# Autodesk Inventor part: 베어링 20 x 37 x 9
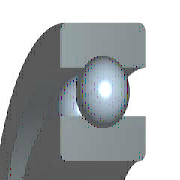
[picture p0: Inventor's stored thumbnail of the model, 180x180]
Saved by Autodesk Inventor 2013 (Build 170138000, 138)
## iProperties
IsCustomPart: 1
Created: 2012-02
Part Number: 베어링 20 x 37 x 9
Material: 강철, 연강
Description: 깊은 그루브 볼 베어링
Document SubType Name: Modeling
Standard: KS B 2023
Designer: mduedu
Standards Organization: KS
Language: ko-KR
Size Designation: 6904 - 20 x 37 x 9
Categories: <MemberInstance><Categories><Category DisplayName="샤프트 부품" InternalName="7f7aeb1f-a693-4053-b835-cee3144e0d98" Mnemonic="SHFT"><Category DisplayName="베어링" Inter
Density: 7.86 g/cm^3
Mass: 36.2614 g
Surface Area: 48.5817 cm^2
Volume: 4.61341 cm^3
Author: mduedu
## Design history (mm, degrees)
sketch "스케치" dims "d0" = 4.42 (= -0.26 x WD + 0.26 x BD)
  geometry: L1 (2.29, 14.25)-(6.71, 14.25); L2 (4.5, 14.25)-(4.5, 12.04); L3 (4.5, 14.25)-(4.5, 16.46); L4 (2.858, 12.771)-(0, 12.771); L5 (0, 10)-(9, 10); L6 (2.858, 15.729)-(0, 15.729); L7 (0, 18.5)-(9, 18.5); L8 (9, 10)-(9, 12.771); L9 (6.142, 12.771)-(9, 12.771); L10 (6.142, 15.729)-(9, 15.729); L11 (9, 18.5)-(9, 15.729); L12 (-1.4, 0)-(8.4, 0) reference; L13 (0, -0.3)-(0, 5.3) reference
  constraints: 22 end point, 4 point on line, 2 collinear, 2 perpendicular, 2 symmetric about line, 1 midpoint, 1 parallel, 14 other
  dimensions: "d9" = 20 diameter of L5 L12 (= WD); "d11" = 37 diameter of L7 L12 (= BD); "d12" = 9 distance between parallel lines of L8 L13 (= KB); "d13" = 25.542 diameter of L9 L12 (= 0.326 x BD + 0.674 x WD)
revolve "본체" stored, may be unused: angle "d6" = 90 deg
revolve "볼" stored, may be unused: angle "d7" = 90 deg
pattern_circular "IDS_ARRAYBALL[SIMPL:T]" dims angle "d3" = 360 deg
body "Solid1"
fillet "모깎기1" dims "d1" = 0.3 (= KRS)
other parameters: "WD" = 20 [user parameter; used in 5 equation terms], "BD" = 37 [user parameter; used in 5 equation terms], "KB" = 9 [user parameter; used in 1 equation term], "KRS" = 0.3 [user parameter; used in 1 equation term], "d4" = 0, "d5" = 0, "d8" = 0, "d14" = 0, "d15" = 0, "BBA" = 0 [user parameter], "BC0" = 3304000 [user parameter], "BC" = 6184000 [user parameter], "BR" = 18.5 (= 0.5 x BD) [user parameter]
